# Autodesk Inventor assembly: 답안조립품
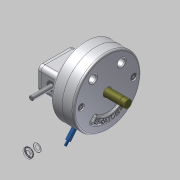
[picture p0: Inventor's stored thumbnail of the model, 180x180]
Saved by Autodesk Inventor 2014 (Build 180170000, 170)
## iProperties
Created: 2015-04
Part Number: 답안조립품
Document SubType Name: Assembly
Designer: Administrator
Author: Administrator
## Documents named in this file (15)
- C:\Documents and Settings\Administrator\바탕 화면\350406V1023\답안조립품.iam
- C:\Documents and Settings\Administrator\바탕 화면\350406V1023\본체.ipt
- C:\Documents and Settings\Administrator\바탕 화면\350406V1023\커버.ipt
- C:\Documents and Settings\Administrator\바탕 화면\350406V1023\M 10 x 35.ipt
- C:\Documents and Settings\Administrator\바탕 화면\350406V1023\커버2.ipt
- C:\Documents and Settings\Administrator\바탕 화면\350406V1023\스프링.ipt
- C:\Documents and Settings\Administrator\바탕 화면\350406V1023\M 5 x 12.ipt
- C:\Documents and Settings\Administrator\바탕 화면\350406V1023\베어링62_22.ipt
- C:\Documents and Settings\Administrator\바탕 화면\350406V1023\축.ipt
- C:\Documents and Settings\Administrator\바탕 화면\350406V1023\멈춤링.ipt
- C:\Documents and Settings\Administrator\바탕 화면\350406V1023\슬라이더2.ipt
- C:\Documents and Settings\Administrator\바탕 화면\350406V1023\슬라이더.ipt
- C:\Documents and Settings\Administrator\바탕 화면\350406V1023\평행핀.ipt
- C:\Documents and Settings\Administrator\바탕 화면\350406V1023\부시.ipt
- C:\Documents and Settings\Administrator\바탕 화면\350406V1023\슬라이더3.ipt
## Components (5 placed, 3 different names)
1. M 10 x 35:1
2. M 10 x 35:2
3. M 5 x 12:1
4. M 5 x 12:2
5. KS B 1320 B B 5 x  20:1
